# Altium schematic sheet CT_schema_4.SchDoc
size 184 x 159 mm
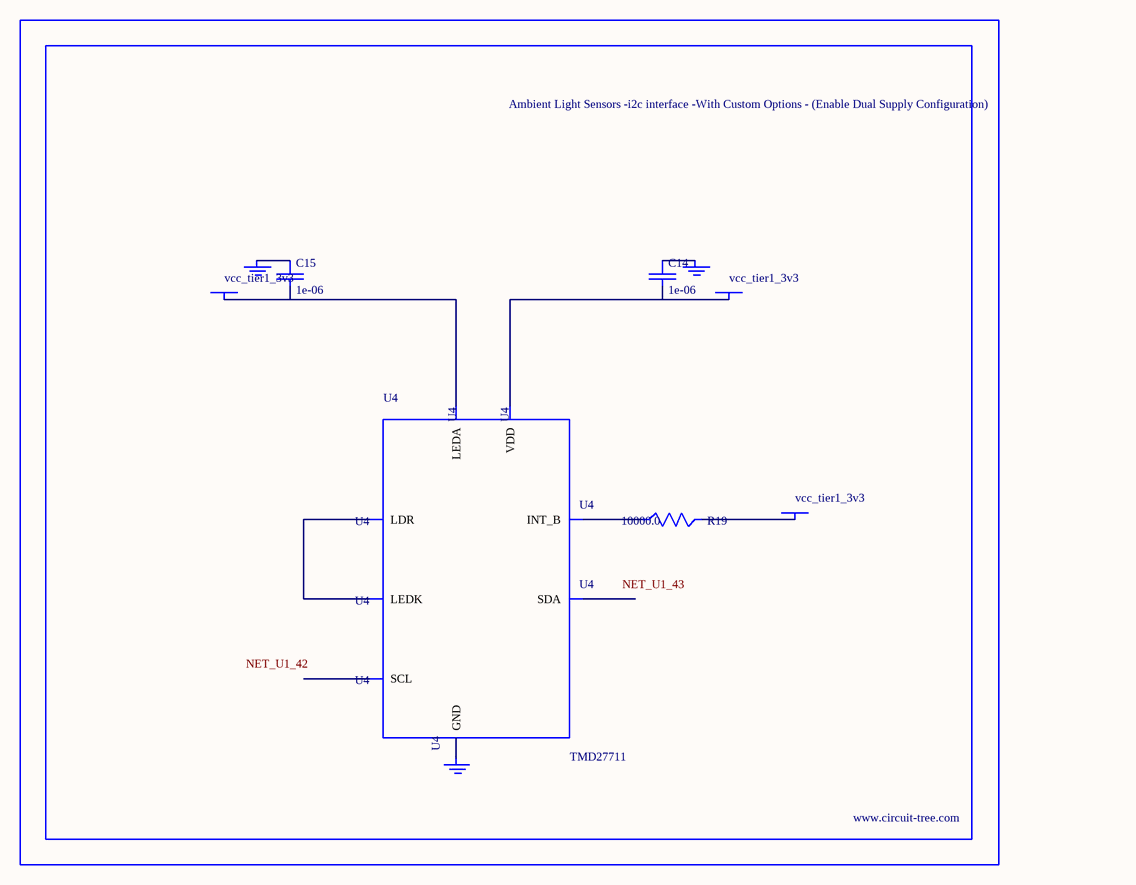
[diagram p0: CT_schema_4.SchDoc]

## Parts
BORDER3  (no value)
C14  1e-06  [C0603]
C15  1e-06  [C0603]
GND_INSTANCE_3_0  (no value)
GND_INSTANCE_3_1  (no value)
GND_INSTANCE_3_2  (no value)
POWER_INSTANCE_3_0  vcc_tier1_3v3
POWER_INSTANCE_3_1  vcc_tier1_3v3
POWER_INSTANCE_3_2  vcc_tier1_3v3
R19  10000.0  [R0603]
U4  TMD27711  [SMD-8]

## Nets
NetC14_1: C14.1 GND_INSTANCE_3_0.0(GND)
NetC14_2: C14.2 POWER_INSTANCE_3_0.0(PWR) U4.1(VDD)
NetC15_1: C15.1 GND_INSTANCE_3_1.0(GND)
NetC15_2: C15.2 POWER_INSTANCE_3_1.0(PWR) U4.4(LEDA)
NetGND_INSTANCE_3_2_0: GND_INSTANCE_3_2.0(GND) U4.3(GND)
NetPOWER_INSTANCE_3_2_0: POWER_INSTANCE_3_2.0(PWR) R19.2
NetR19_1: R19.1 U4.7(INT_B)
NetU4_5: U4.5(LEDK) U4.6(LDR)

Not connected (* = marked no-connect by the designer): U4 2(SCL) 8(SDA)

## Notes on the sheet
- Labels drawn without touching a wire or pin: NET_U1_42, NET_U1_43

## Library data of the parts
BORDER3 = BORDER_PAGE3
C14 C15 = C0603C105K3RACTU
GND_INSTANCE_3_0-GND_INSTANCE_3_2 = GND
POWER_INSTANCE_3_0-POWER_INSTANCE_3_2 = PWR
R19 = RC0603JR-0710KL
